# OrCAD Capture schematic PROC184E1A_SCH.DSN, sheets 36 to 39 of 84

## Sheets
36 40. RESET INPUTS: size C; title: RESET INPUTS; note: PROC184_SCH
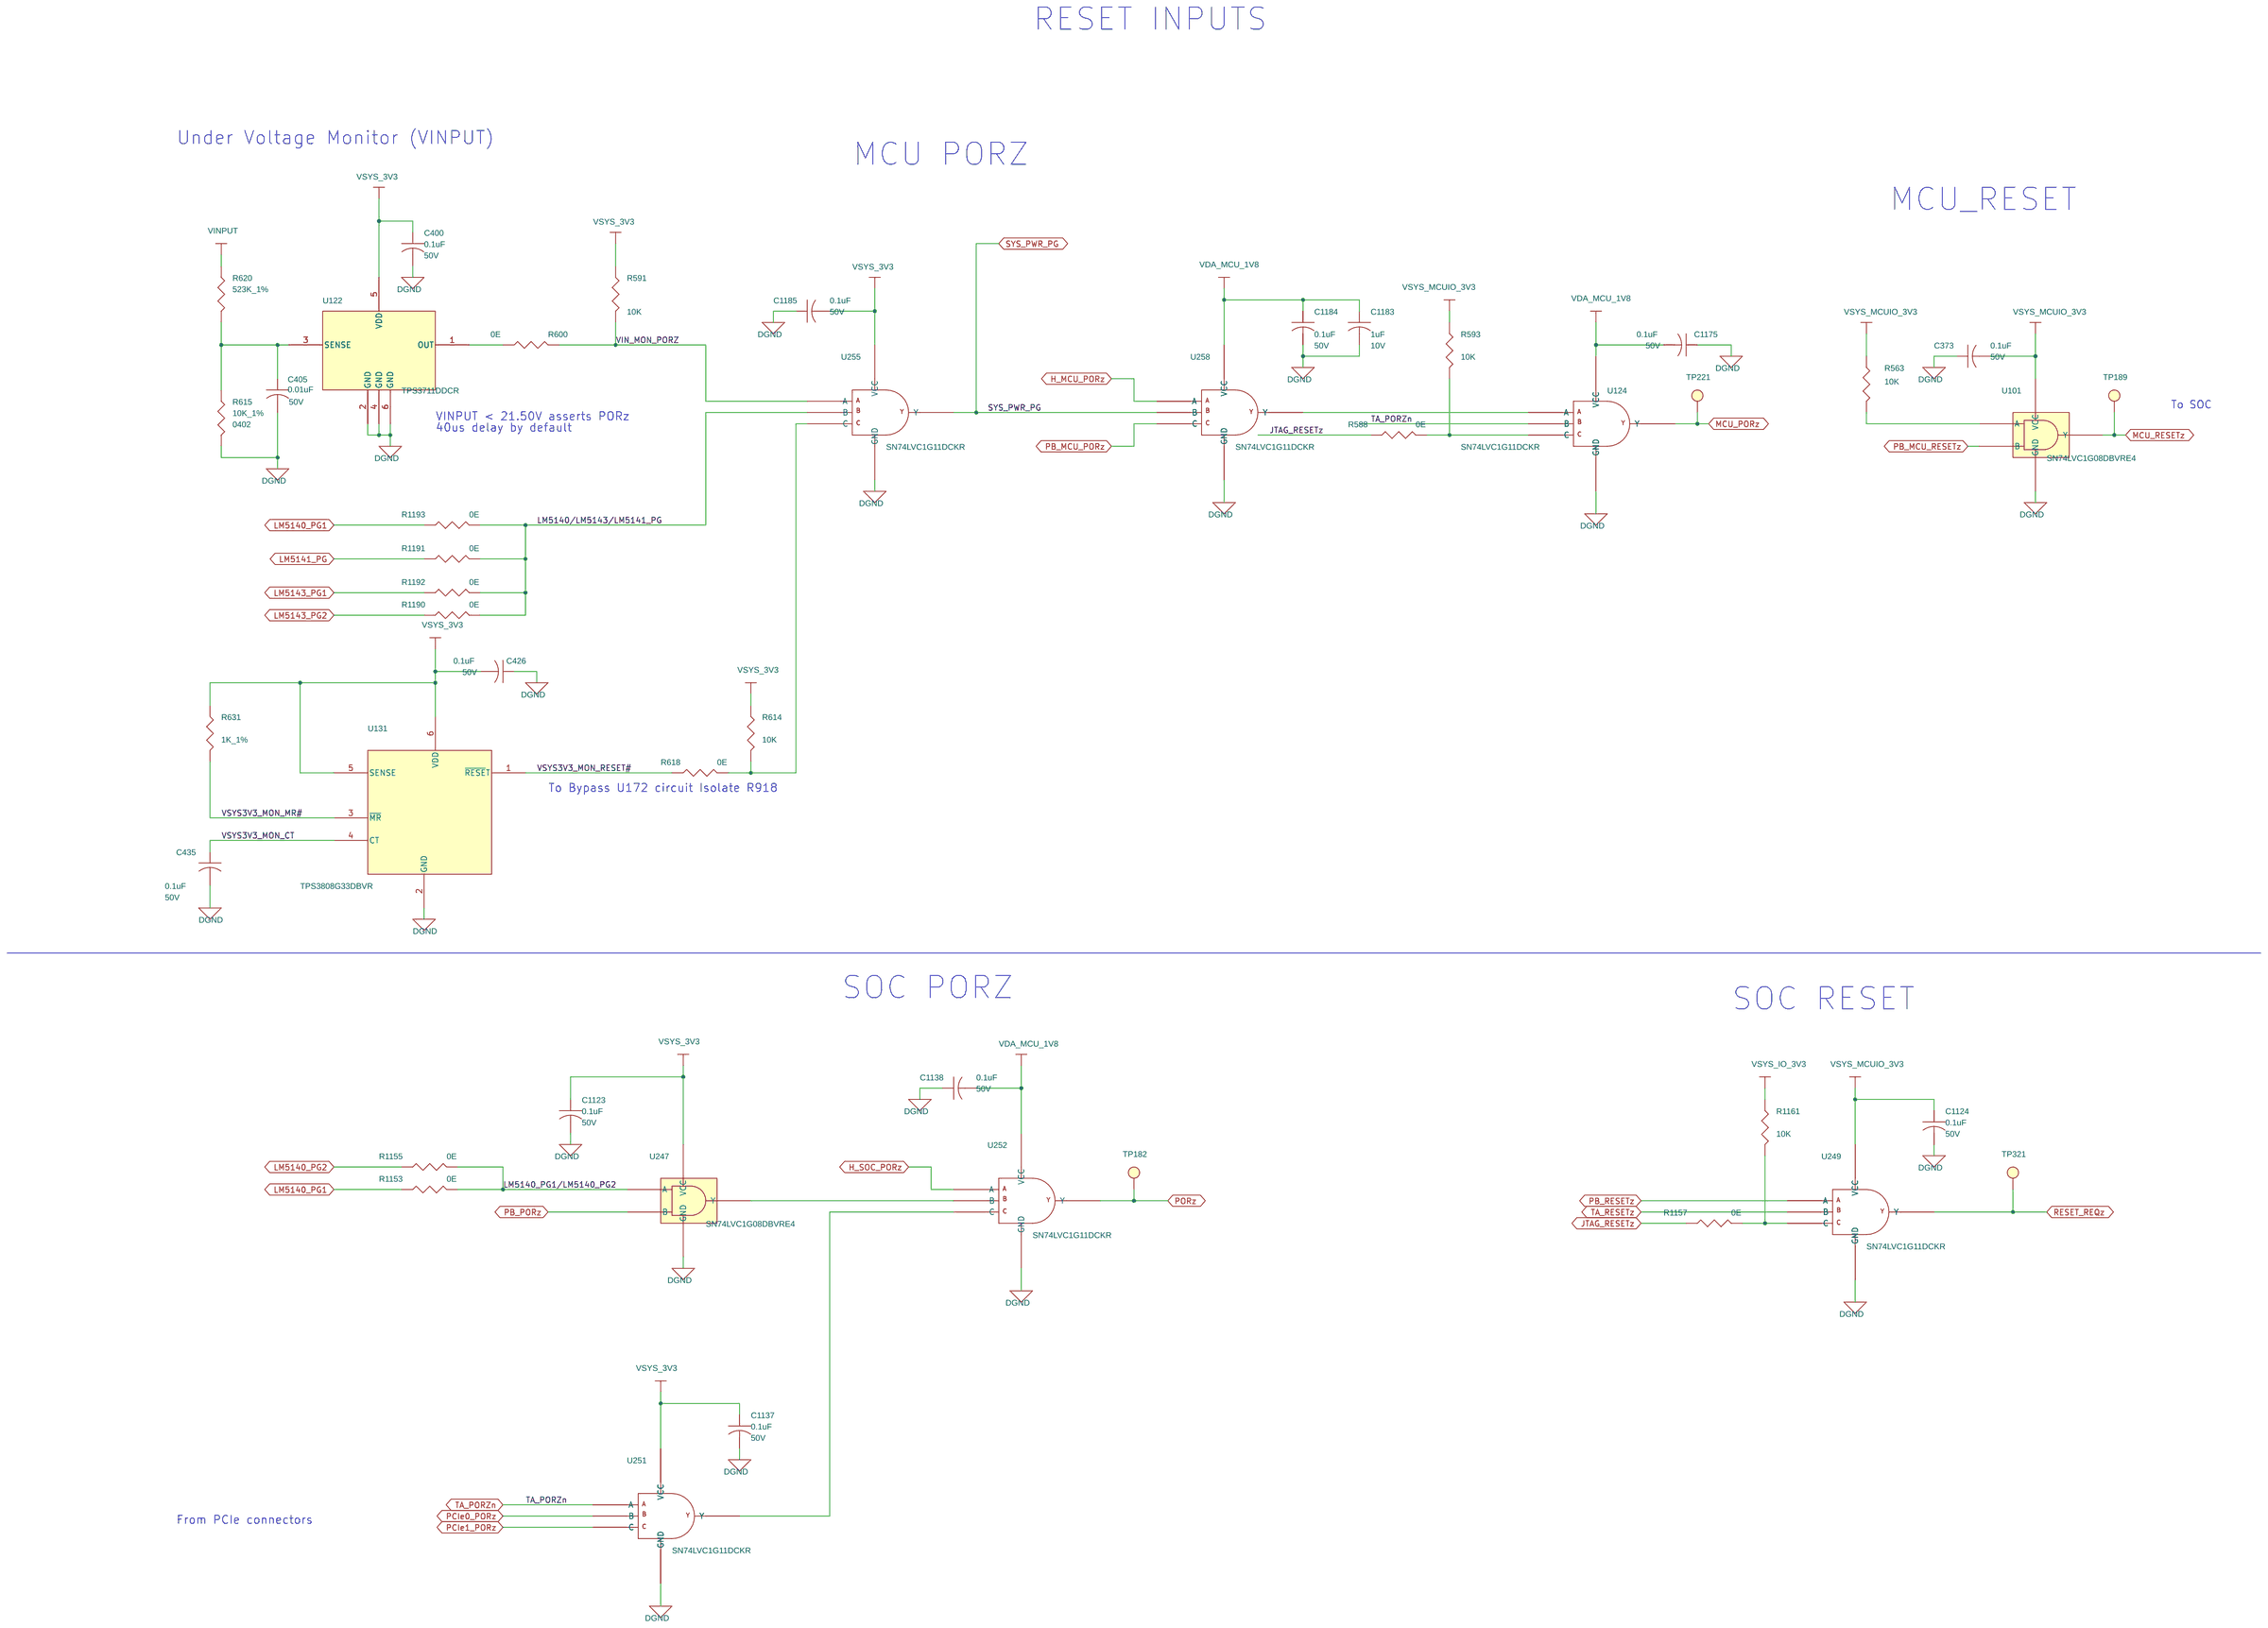
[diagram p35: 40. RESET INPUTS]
37 41. RESET OUTPUTS: size C; title: RESET OUTPUTS; note: PROC184_SCH
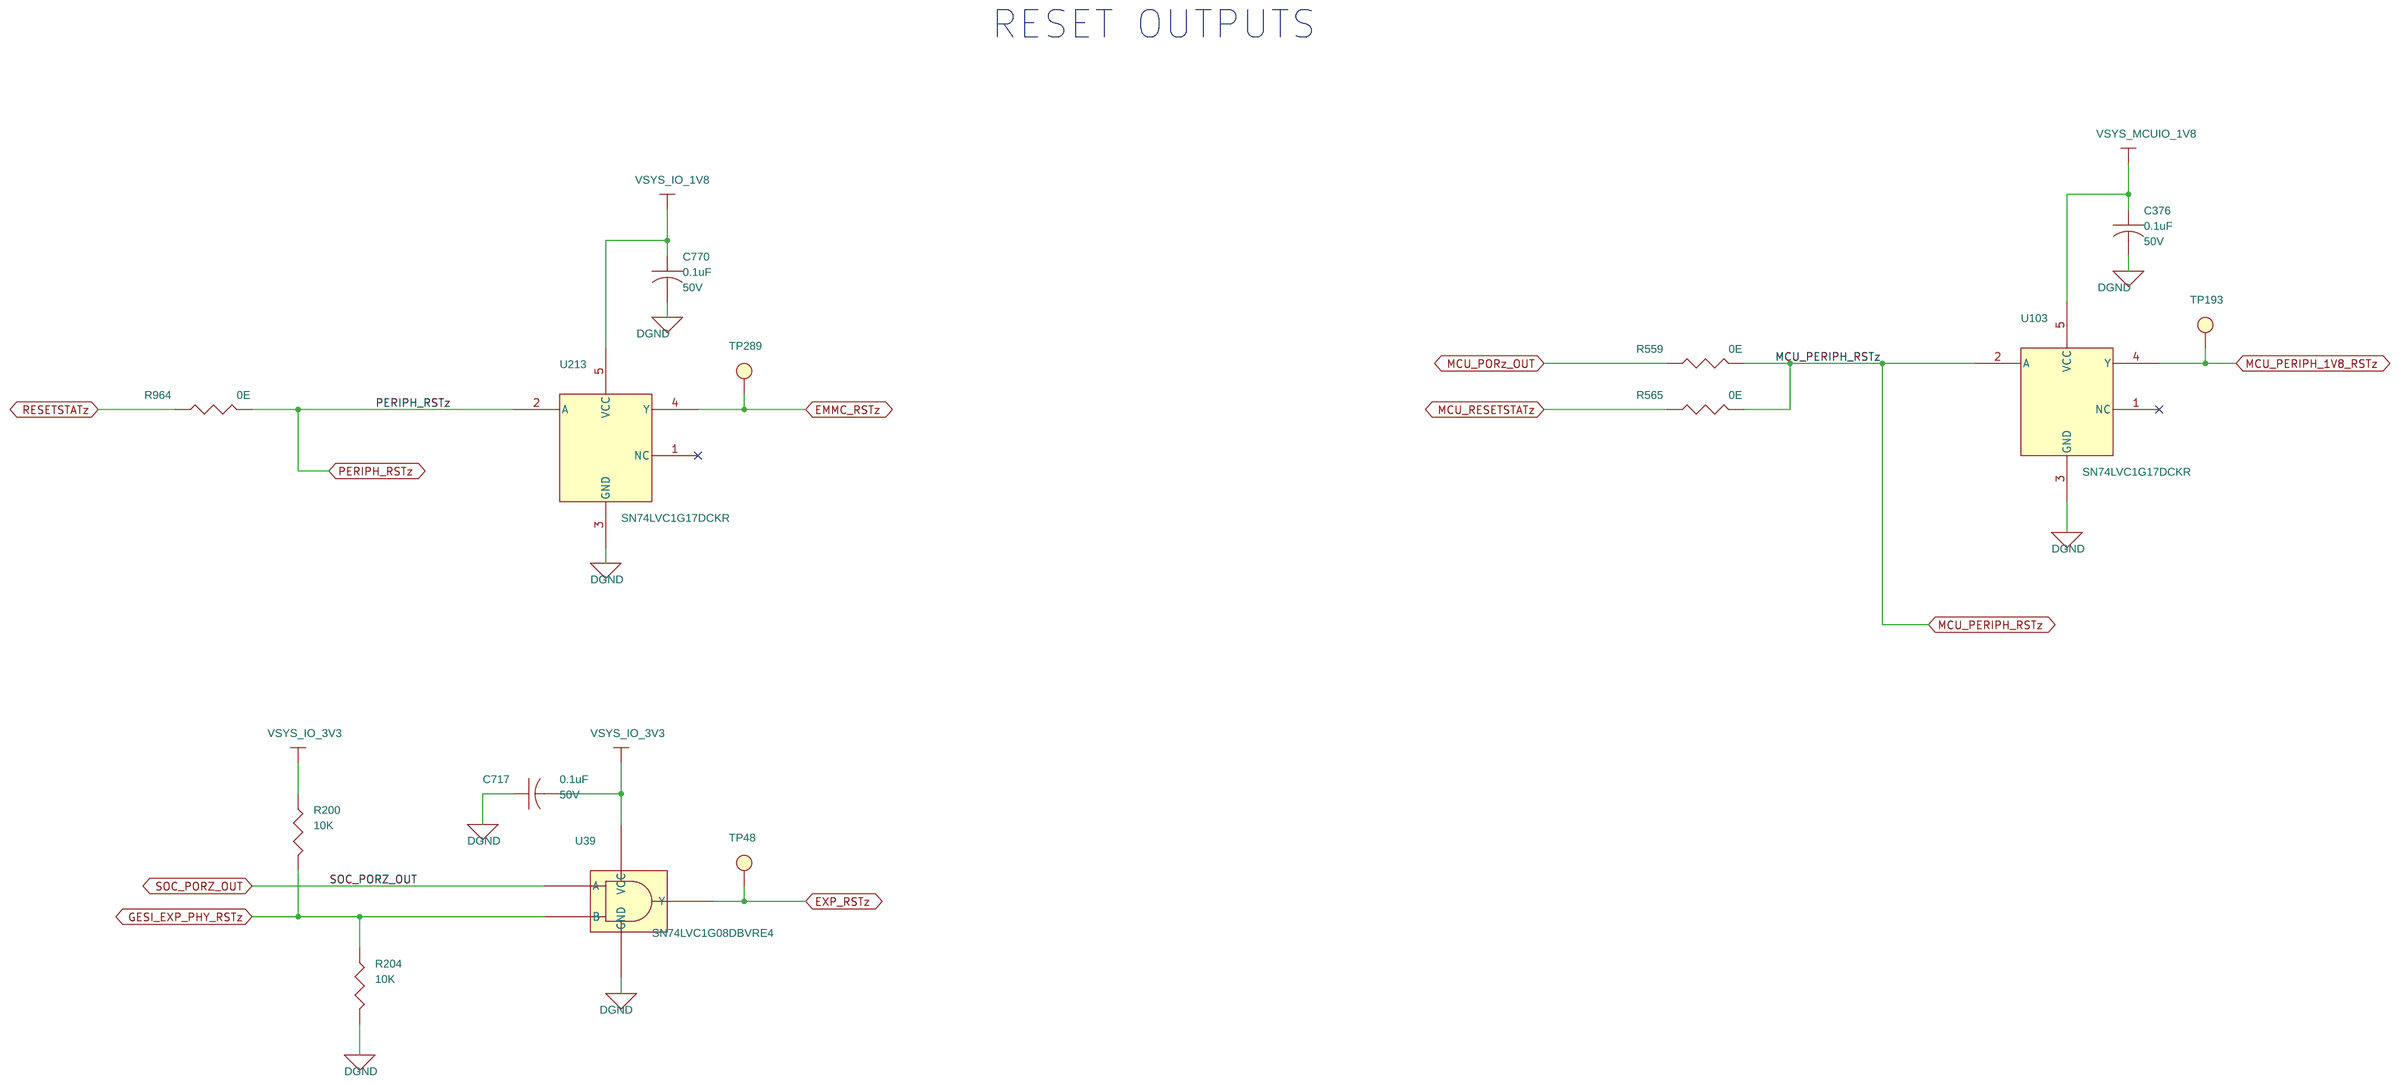
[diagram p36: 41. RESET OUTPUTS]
38 42. GPIO EXPANDERS: size C; title: GPIO  EXPANDERS; note: PROC184_SCH
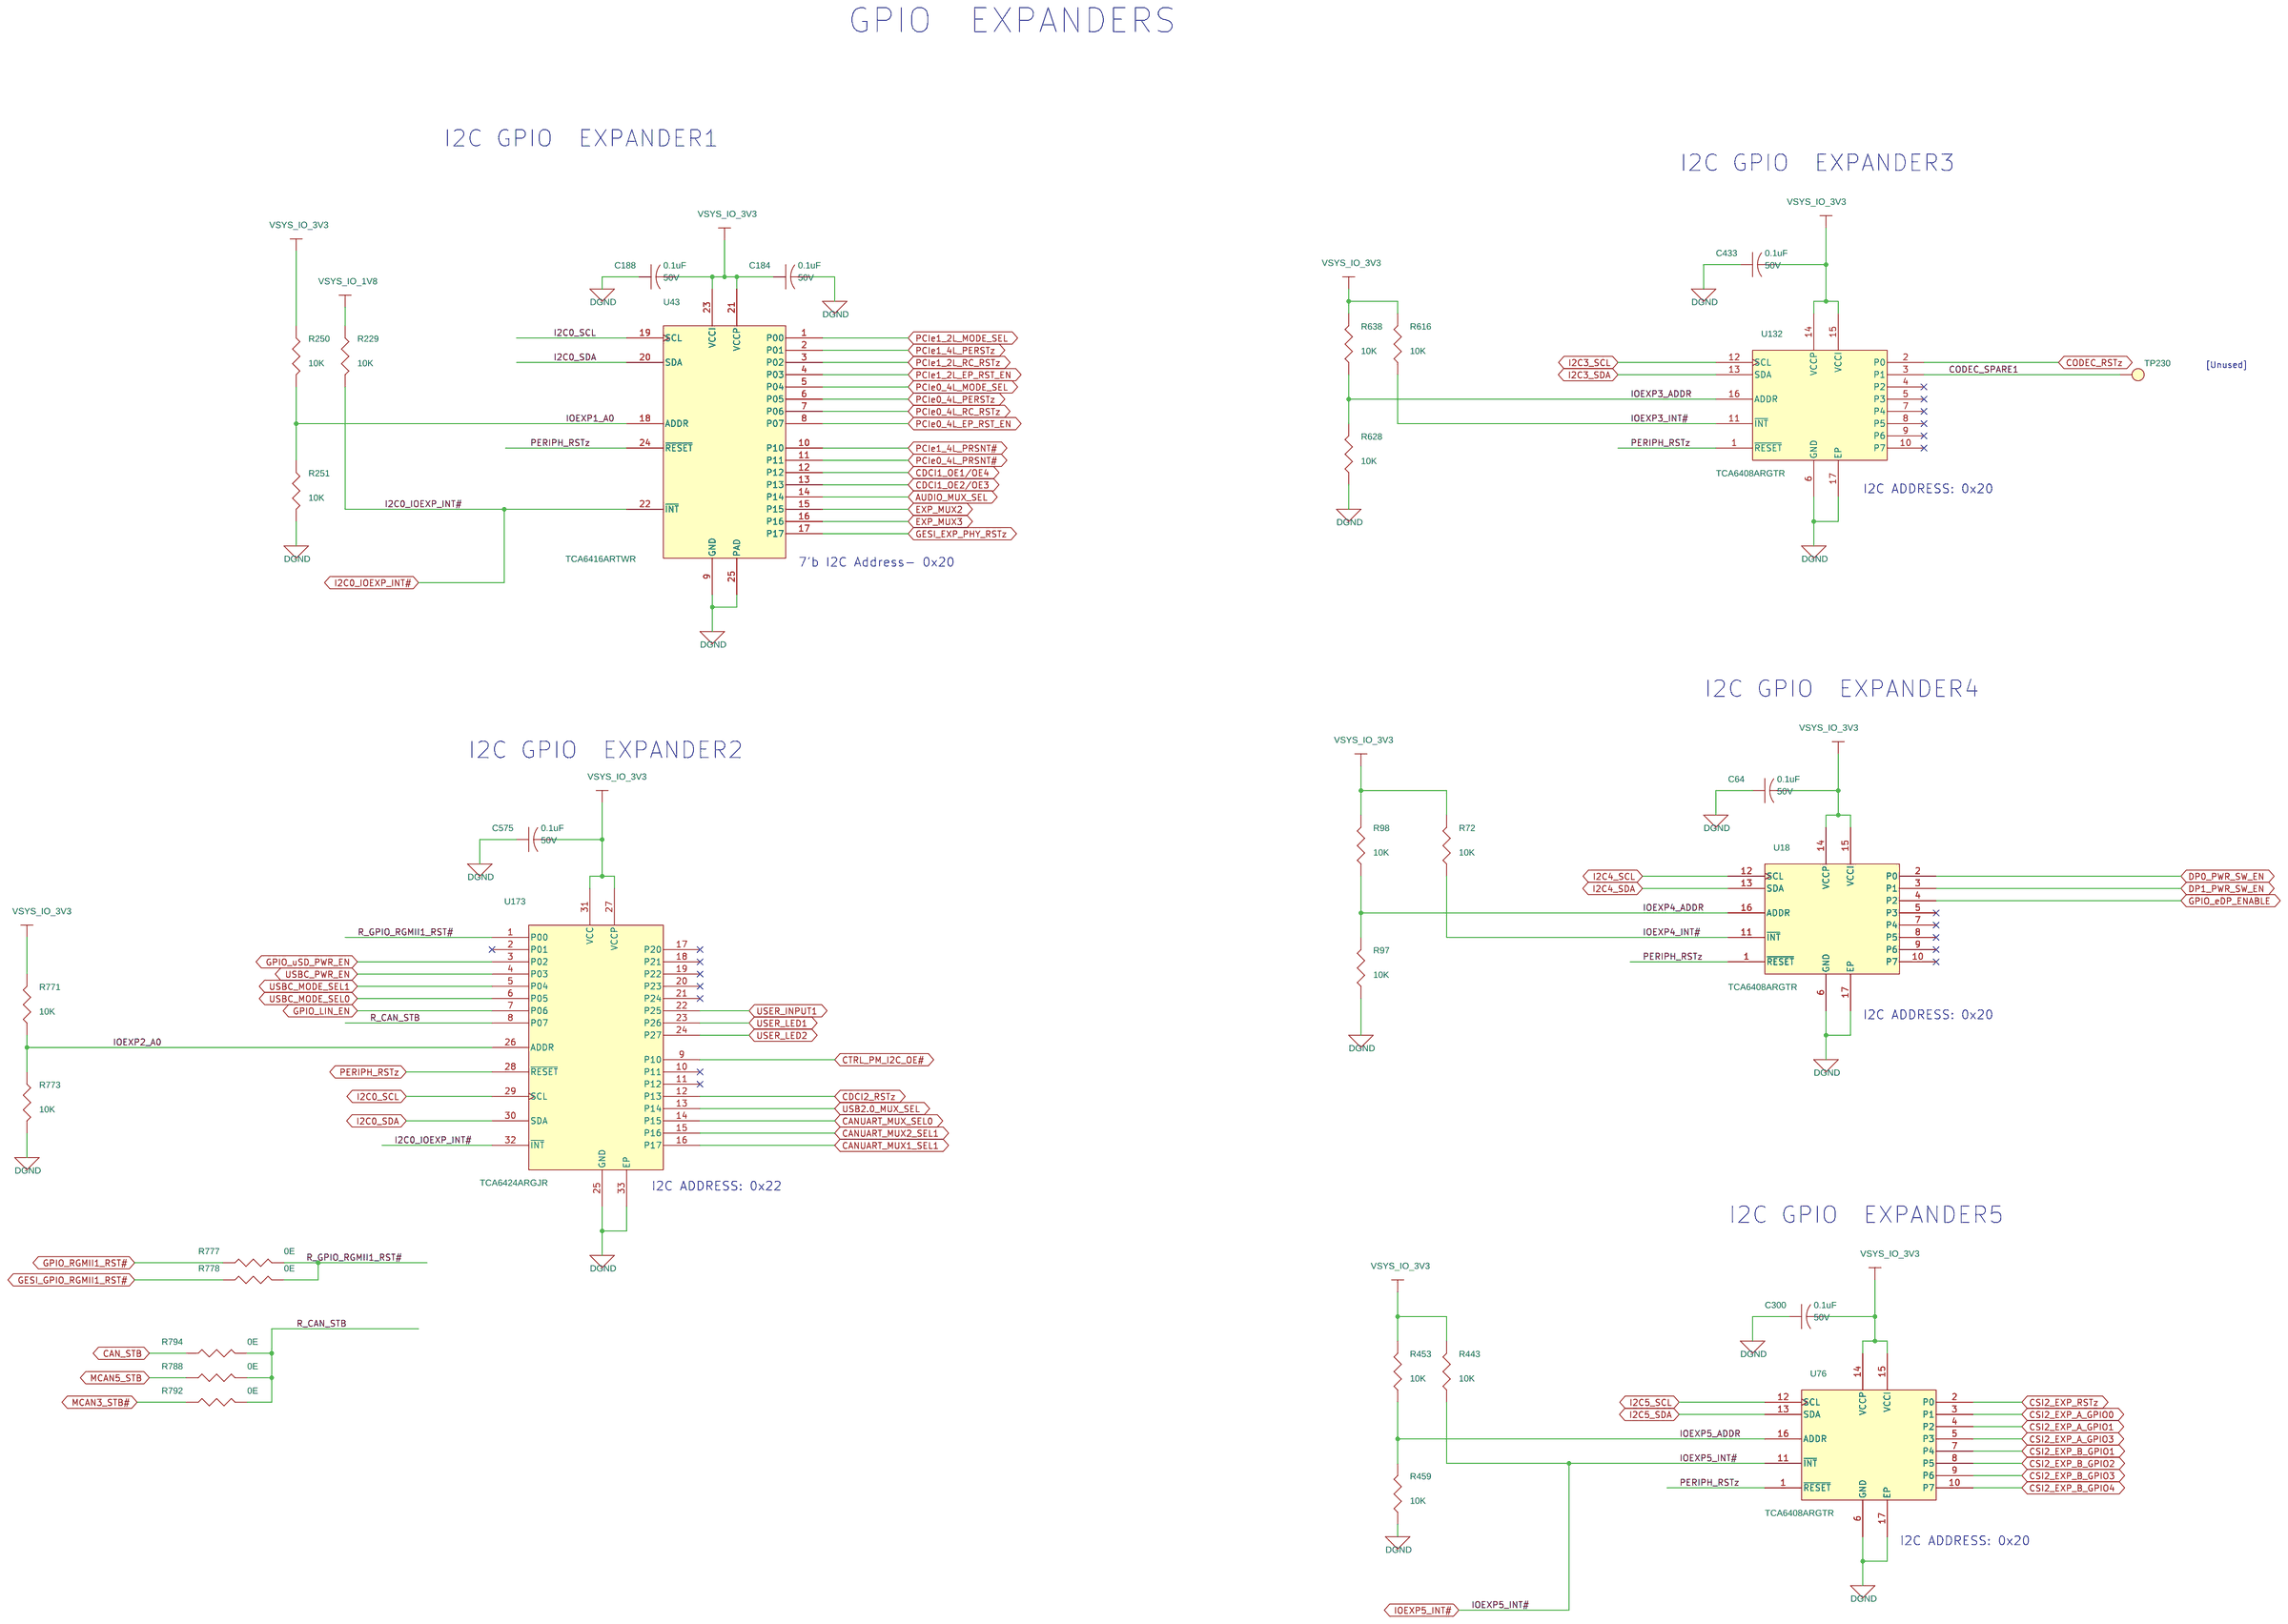
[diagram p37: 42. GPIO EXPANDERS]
39 43. SPI NOR FLASH: size C; title: SPI NOR FLASH; note: PROC184_SCH
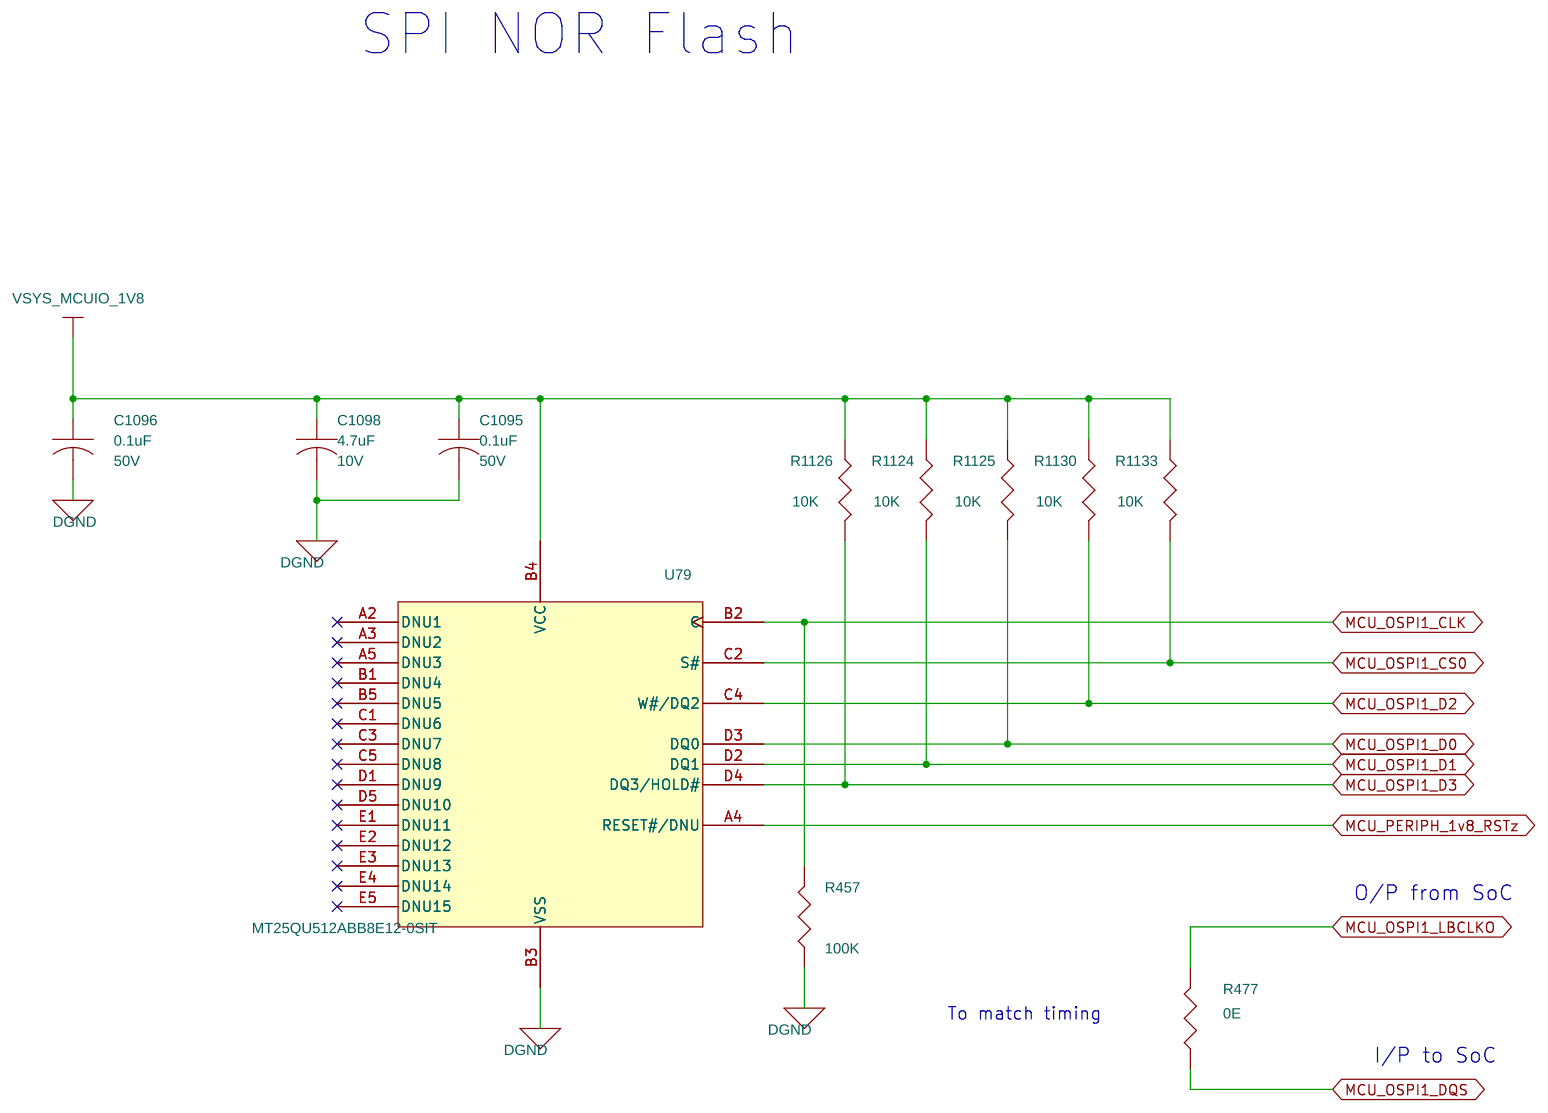
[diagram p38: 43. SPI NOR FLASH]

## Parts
sheet 40. RESET INPUTS
C373  0.1uF  [CAP0402_0-75]
C400  0.1uF  [CAP0402_0-75]
C405  0.01uF  [CAP0402_0-75]
C426  0.1uF  [CAP0402_0-75]
C435  0.1uF  [CAP0402_0-75]
C1123  0.1uF  [CAP0402_0-75]
C1124  0.1uF  [CAP0402_0-75]
C1137  0.1uF  [CAP0402_0-75]
C1138  0.1uF  [CAP0402_0-75]
C1175  0.1uF  [CAP0402_0-75]
C1183  1uF  [CAP0402_0-75]
C1184  0.1uF  [CAP0402_0-75]
C1185  0.1uF  [CAP0402_0-75]
R563  10K  [RES0402_0-5]
R588  0E  [RES0402_0-5]
R591  10K  [RES0402_0-5]
R593  10K  [RES0402_0-5]
R600  0E  [RES0402_0-5]
R614  10K  [RES0402_0-5]
R615  10K_1%  [RES0402_0-5]
R618  0E  [RES0402_0-5]
R620  523K_1%  [RES0402_0-5]
R631  1K_1%  [RES0402_0-5]
R1153  0E  [RES0402_0-5]
R1155  0E  [RES0402_0-5]
R1157  0E  [RES0402_0-5]
R1161  10K  [RES0402_0-5]
R1190  0E  [RES0402_0-5]
R1191  0E  [RES0402_0-5]
R1192  0E  [RES0402_0-5]
R1193  0E  [RES0402_0-5]
TP182  TP40_SMD  [TP40_SMD]
TP189  TP40_SMD  [TP40_SMD]
TP221  TP40_SMD  [TP40_SMD]
TP321  TP40_SMD  [TP40_SMD]
U101  SN74LVC1G08DBVRE4  [SOT23-5]
U122  TPS3711DDCR  [SOT23-6_1-1]
U124  SN74LVC1G11DCKR  [SC70-6]
U131  TPS3808G33DBVR  [SOT23-6_1-5]
U247  SN74LVC1G08DBVRE4  [SOT23-5]
U249  SN74LVC1G11DCKR  [SC70-6]
U251  SN74LVC1G11DCKR  [SC70-6]
U252  SN74LVC1G11DCKR  [SC70-6]
U255  SN74LVC1G11DCKR  [SC70-6]
U258  SN74LVC1G11DCKR  [SC70-6]
sheet 41. RESET OUTPUTS
C376  0.1uF  [CAP0402_0-75]
C717  0.1uF  [CAP0402_0-75]
C770  0.1uF  [CAP0402_0-75]
R200  10K  [RES0402_0-5]
R204  10K  [RES0402_0-5]
R559  0E  [RES0402_0-5]
R565  0E  [RES0402_0-5]
R964  0E  [RES0402_0-5]
TP48  TP40_SMD  [TP40_SMD]
TP193  TP40_SMD  [TP40_SMD]
TP289  TP40_SMD  [TP40_SMD]
U39  SN74LVC1G08DBVRE4  [SOT23-5]
U103  SN74LVC1G17DCKR  [SC70-5]
U213  SN74LVC1G17DCKR  [SC70-5]
sheet 42. GPIO EXPANDERS
C64  0.1uF  [CAP0402_0-75]
C184  0.1uF  [CAP0402_0-75]
C188  0.1uF  [CAP0402_0-75]
C300  0.1uF  [CAP0402_0-75]
C433  0.1uF  [CAP0402_0-75]
C575  0.1uF  [CAP0402_0-75]
R72  10K  [RES0402_0-5]
R97  10K  [RES0402_0-5]
R98  10K  [RES0402_0-5]
R229  10K  [RES0402_0-5]
R250  10K  [RES0402_0-5]
R251  10K  [RES0402_0-5]
R443  10K  [RES0402_0-5]
R453  10K  [RES0402_0-5]
R459  10K  [RES0402_0-5]
R616  10K  [RES0402_0-5]
R628  10K  [RES0402_0-5]
R638  10K  [RES0402_0-5]
R771  10K  [RES0402_0-5]
R773  10K  [RES0402_0-5]
R777  0E  [RES0201_0-5]
R778  0E  [RES0201_0-5]
R788  0E  [RES0402_0-5]
R792  0E  [RES0402_0-5]
R794  0E  [RES0402_0-5]
TP230  TP40_SMD  [TP40_SMD]
U18  TCA6408ARGTR  [QFN16_19-68_120X120_1_EP1-6]
U43  TCA6416ARTWR  [WQFN24_19-68_160X160]
U76  TCA6408ARGTR  [QFN16_19-68_120X120_1_EP1-6]
U132  TCA6408ARGTR  [QFN16_19-68_120X120_1_EP1-6]
U173  TCA6424ARGJR  [QFN32_19-68_200X200]
sheet 43. SPI NOR FLASH
C1095  0.1uF  [CAP0402_0-75]
C1096  0.1uF  [CAP0402_0-75]
C1098  4.7uF  [CAP0402_0-75]
R457  100K  [RES0402_0-5]
R477  0E  [RES0402_0-5]
R1124  10K  [RES0402_0-5]
R1125  10K  [RES0402_0-5]
R1126  10K  [RES0402_0-5]
R1130  10K  [RES0402_0-5]
R1133  10K  [RES0402_0-5]
U79  MT25QU512ABB8E12-0SIT  [TPBGA24_39-37_240X320_1-2]

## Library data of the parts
C64 C184 C188 C300 C373 C376 C400 C426 C433 C575 C717 C770 C1095 C1096 C1123 C1124 C1137 C1138 C1175 C1184 C1185 = CAP: CAP CERAMIC 0.1uF 50V 10% X7R 0402; Automotive Alternate_mfr_name: TDK; Automotive Alternate_mfr_part_number: CGA2B3X7R1H104K050BB; Chkd/date: MANIRAJA/261020; Crtd /date: ALVY/211020; Custom_Duty: 15%; Customs_HS_Code: 85322990; Direct Alternate_mfr_name: TDK; Direct Alternate_mfr_part_number: C1005X7R1H104K050BE; Distributor_name: DIGIKEY; Distributor_part_number: 490-10700-1-ND; Footprint Path: Y:\MIS_DATABASE\Library\ALTIUM_TOOL\PCB_FOOTPRINTS\Altium_Footprint_Lib.PcbLib; Height: 0.55MM; Library Path: Y:\MIS_DATABASE\Library\ALTIUM_TOOL\SCHEMATICS_PARTS\MS_DISCRETE_Library.schlib; Manufacturer: MURATA; Mfr_name: MURATA; Mfr_part_number: GRM155R71H104KE14D; Mistral Part No: 120011100014-R; Package: 0402; Part_type: CAPACITORS\CERAMIC; Project: J7_CP; RoHS: RoHS; Temperature: -55°C+125°C; Tolerance: 10%; Voltage: 50V; Wattage: NA; Weight: 3.1mg; Datasheet: Y:\MIS_DATABASE\DATASHEETS\CAPACITORS\GRM155R71H104KE14.PDF
C405 = CAP: CAP CERAMIC 0.01uF 50V 10% X7R 0402; Automotive Alternate_mfr_name: TDK; Automotive Alternate_mfr_part_number: CGA2B2X7R1E103K050BA; Chkd/date: MANIRAJA/280319; Crtd /date: MANIRAJA/280319; Custom_Duty: 15%; Customs_HS_Code: 85322990; Direct Alternate_mfr_name: YAGEO AMERICA; Direct Alternate_mfr_part_number: CC0402KRX7R8BB103; Distributor_name: DIGIKEY; Distributor_part_number: 490-4516-1-ND; Footprint Path: Y:\MIS_DATABASE\Library\ALTIUM_TOOL\PCB_FOOTPRINTS\Altium_Footprint_Lib.PcbLib; Height: 0.55MM; Library Path: Y:\MIS_DATABASE\Library\ALTIUM_TOOL\SCHEMATICS_PARTS\MS_DISCRETE_Library.schlib; Manufacturer: MURATA; Mfr_name: MURATA; Mfr_part_number: GRM155R71H103KA88D; Mistral Part No: 120009030025-R; Package: 0402; Part_type: CAPACITORS\CERAMIC; Project: G4_SVGA; RoHS: RoHS; Temperature: -55°C+125°C; Tolerance: 10%; Voltage: 50V; Wattage: NA; Weight: 0.65mg; Datasheet: Y:\MIS_DATABASE\DATASHEETS\CAPACITORS\GRM155R71H103KA88D.PDF
C435 = CAP: CAP CERAMIC 0.1uF 50V 10% X7R 0402; Assembly_Instruction: DNI; Automotive Alternate_mfr_name: TDK; Automotive Alternate_mfr_part_number: CGA2B3X7R1H104K050BB; Chkd/date: MANIRAJA/261020; Crtd /date: ALVY/211020; Custom_Duty: 15%; Customs_HS_Code: 85322990; Direct Alternate_mfr_name: TDK; Direct Alternate_mfr_part_number: C1005X7R1H104K050BE; Distributor_name: DIGIKEY; Distributor_part_number: 490-10700-1-ND; Footprint Path: Y:\MIS_DATABASE\Library\ALTIUM_TOOL\PCB_FOOTPRINTS\Altium_Footprint_Lib.PcbLib; Height: 0.55MM; Library Path: Y:\MIS_DATABASE\Library\ALTIUM_TOOL\SCHEMATICS_PARTS\MS_DISCRETE_Library.schlib; Manufacturer: MURATA; Mfr_name: MURATA; Mfr_part_number: GRM155R71H104KE14D; Mistral Part No: 120011100014-R; Package: 0402; Part_type: CAPACITORS\CERAMIC; Project: J7_CP; RoHS: RoHS; Temperature: -55°C+125°C; Tolerance: 10%; Voltage: 50V; Wattage: NA; Weight: 3.1mg; Datasheet: Y:\MIS_DATABASE\DATASHEETS\CAPACITORS\GRM155R71H104KE14.PDF
C1183 = CAP: CAP CERAMIC 1uF 10V 10% X7S AUTO 0402; Automotive Alternate_mfr_name: TAIYO YUDEN; Automotive Alternate_mfr_part_number: EMK105BJ105KVHF; Chkd/date: MANIRAJA/100918; Crtd /date: ALVY/100918; Custom_Duty: 15%; Customs_HS_Code: 85322990; Direct Alternate_mfr_name: YAGEO AMERICA; Direct Alternate_mfr_part_number: CC0402KRX5R7BB105; Distributor_name: DIGIKEY; Distributor_part_number: 490-13409-1-ND; Footprint Path: Y:\MIS_DATABASE\Library\ALTIUM_TOOL\PCB_FOOTPRINTS\Altium_Footprint_Lib.PcbLib; Height: 0.70MM; Library Path: Y:\MIS_DATABASE\Library\ALTIUM_TOOL\SCHEMATICS_PARTS\MS_DISCRETE_Library.schlib; Manufacturer: TDK CORPORATION; Mfr_name: MURATA; Mfr_part_number: GCM155C71A105KE38D; Mistral Part No: 120018090021-R; Package: 0402; Part_type: CAPACITORS\CERAMIC; Project: SMART-M_SCRIPTALK_PB; RoHS: RoHS; Temperature: -55°C+125°C; Tolerance: 10%; Voltage: 10V; Wattage: NA; Weight: 6mg; Datasheet: Y:\MIS_DATABASE\DATASHEETS\CAPACITORS\MURATA-GCM-SER.PDF
R72 R97 R200 R229 R251 R443 R459 R563 R591 R593 R614 R616 R628 R773 R1126 R1130 R1133 R1161 = RESISTOR: RES 10K 1/16W 5% 0402; Chkd/date: VASANTHA/061216; Crtd /date: MAZHAR/230805; Custom_Duty: 15%; Customs_HS_Code: 85332119; Distributor_name: DIGIKEY; Distributor_part_number: 311-10KJRCT-ND; Footprint Path: Y:\MIS_DATABASE\Library\ALTIUM_TOOL\PCB_FOOTPRINTS\Altium_Footprint_Lib.PcbLib; Height: 0.40MM; Library Path: Y:\MIS_DATABASE\Library\ALTIUM_TOOL\SCHEMATICS_PARTS\MS_DISCRETE_Library.schlib; Manufacturer: YAGEO AMERICA; Mfr_name: YAGEO AMERICA; Mfr_part_number: RC0402JR-0710KL; Mistral Part No: 110011060021-R; Package: 0402; Part_type: RESISTORS\FIXED; Project: HSE; RoHS: RoHS; Temperature: -55°C+155°C; Tolerance: 5%; Voltage: NA; Wattage: 1/16W; Weight: 0.65mg; Datasheet: Y:\MIS_DATABASE\DATASHEETS\RESISTORS\RCXXXXL-SER_MAR18.PDF
R477 R565 R588 R600 R618 R788 R792 R794 R964 R1153 R1155 R1157 R1190 R1192 R1193 = RESISTOR: RES 0E 1/10W JUMPER 0402; Chkd/date: VASANTHA/061216; Crtd /date: NAVEED/201014; Custom_Duty: 15%; Customs_HS_Code: 85332119; Distributor_name: DIGIKEY; Distributor_part_number: P0.0JCT-ND; Footprint Path: Y:\MIS_DATABASE\Library\ALTIUM_TOOL\PCB_FOOTPRINTS\Altium_Footprint_Lib.PcbLib; Height: 0.40MM; IBISSP_MODLES: VALUE REPEATING 2 TIME; Library Path: Y:\MIS_DATABASE\Library\ALTIUM_TOOL\SCHEMATICS_PARTS\MS_DISCRETE_Library.schlib; Manufacturer: PANASONIC-ECG; Mfr_name: PANASONIC-ECG; Mfr_part_number: ERJ-2GE0R00X; Mistral Part No: 110018030052-R; Package: 0402; Part_type: RESISTORS\FIXED; Project: AEGIS POM; RoHS: RoHS; Temperature: -55°C+155°C; Tolerance: NA; Voltage: NA; Wattage: 1/10W; Weight: 0.8mg; Datasheet: Y:\MIS_DATABASE\DATASHEETS\RESISTORS\PAN-ERJSER_NOV17.PDF
R615 = RESISTOR: RES 10K 1/16W 1% 0402; Chkd/date: VASANTHA/201216; Crtd /date: GEETHA/290506; Custom_Duty: 15%; Customs_HS_Code: 85332119; Distributor_name: DIGIKEY; Distributor_part_number: 311-10.0KLRTR-ND; Footprint Path: Y:\MIS_DATABASE\Library\ALTIUM_TOOL\PCB_FOOTPRINTS\Altium_Footprint_Lib.PcbLib; Height: 0.40MM; Library Path: Y:\MIS_DATABASE\Library\ALTIUM_TOOL\SCHEMATICS_PARTS\MS_DISCRETE_Library.schlib; Manufacturer: YAGEO AMERICA; Mfr_name: YAGEO AMERICA; Mfr_part_number: RC0402FR-0710KL; Mistral Part No: 110015090015-R; Package: 0402; Part_type: RESISTORS\FIXED; Project: VOCERA; RoHS: RoHS; Temperature: -55°C+155°C; Tolerance: 1%; Voltage: NA; Wattage: 1/16W; Weight: 0.65mg; Datasheet: Y:\MIS_DATABASE\DATASHEETS\RESISTORS\RCXXXXL-SER_MAR18.PDF
R620 = RESISTOR: RES 523K 1/10W 1% 0402; Chkd/date: MANIRAJA/111219; Crtd /date: ALVY/111219; Custom_Duty: 15%; Customs_HS_Code: 85332119; Distributor_name: DIGIKEY; Distributor_part_number: P523KLCT-ND; Footprint Path: Y:\MIS_DATABASE\Library\ALTIUM_TOOL\PCB_FOOTPRINTS\Altium_Footprint_Lib.PcbLib; Height: 0.40MM; Library Path: Y:\MIS_DATABASE\Library\ALTIUM_TOOL\SCHEMATICS_PARTS\MS_DISCRETE_Library.schlib; Manufacturer: PANASONIC-ECG; Mfr_name: PANASONIC-ECG; Mfr_part_number: ERJ-2RKF5233X; Mistral Part No: 110019120010-R; Package: 0402; Part_type: RESISTORS\FIXED; Project: CLOUD RADAR_CONTROLLER-PS_BRD; RoHS: RoHS; Temperature: -55°C+155°C; Tolerance: 1%; Voltage: NA; Wattage: 1/10W; Weight: 0.8mg; Datasheet: Y:\MIS_DATABASE\DATASHEETS\RESISTORS\PAN-ERJSER_NOV17.PDF
R631 = RESISTOR: RES 1K 1/10W 1% 0402; Chkd/date: VASANTHA/281216; Crtd /date: MAZHAR/150506; Custom_Duty: 15%; Customs_HS_Code: 85332119; Distributor_name: DIGIKEY; Distributor_part_number: P1.00KLCT-ND; Footprint Path: Y:\MIS_DATABASE\Library\ALTIUM_TOOL\PCB_FOOTPRINTS\Altium_Footprint_Lib.PcbLib; Height: 0.40MM; Library Path: Y:\MIS_DATABASE\Library\ALTIUM_TOOL\SCHEMATICS_PARTS\MS_DISCRETE_Library.schlib; Manufacturer: PANASONIC-ECG; Mfr_name: PANASONIC-ECG; Mfr_part_number: ERJ-2RKF1001X; Mistral Part No: 110009030411-R; Package: 0402; Part_type: RESISTORS\FIXED; Project: VOCERA; RoHS: RoHS; Temperature: -55°C+155°C; Tolerance: 1%; Voltage: NA; Wattage: 1/10W; Weight: 0.8mg; Datasheet: Y:\MIS_DATABASE\DATASHEETS\RESISTORS\PAN-ERJSER_NOV17.PDF
R559 R1191 = RESISTOR: RES 0E 1/10W JUMPER 0402; Assembly_Instruction: DNI; Chkd/date: VASANTHA/061216; Crtd /date: NAVEED/201014; Custom_Duty: 15%; Customs_HS_Code: 85332119; Distributor_name: DIGIKEY; Distributor_part_number: P0.0JCT-ND; Footprint Path: Y:\MIS_DATABASE\Library\ALTIUM_TOOL\PCB_FOOTPRINTS\Altium_Footprint_Lib.PcbLib; Height: 0.40MM; IBISSP_MODLES: VALUE REPEATING 2 TIME; Library Path: Y:\MIS_DATABASE\Library\ALTIUM_TOOL\SCHEMATICS_PARTS\MS_DISCRETE_Library.schlib; Manufacturer: PANASONIC-ECG; Mfr_name: PANASONIC-ECG; Mfr_part_number: ERJ-2GE0R00X; Mistral Part No: 110018030052-R; Package: 0402; Part_type: RESISTORS\FIXED; Project: AEGIS POM; RoHS: RoHS; Temperature: -55°C+155°C; Tolerance: NA; Voltage: NA; Wattage: 1/10W; Weight: 0.8mg; Datasheet: Y:\MIS_DATABASE\DATASHEETS\RESISTORS\PAN-ERJSER_NOV17.PDF
TP48 TP182 TP189 TP193 TP221 TP230 TP289 TP321 = TESTPOINT: TESTPOINT CIR 40 SMD; Chkd/date: MAZHAR/190505; Crtd /date: MAZHAR/190505; Distributor_name: NA; Distributor_part_number: NA; Footprint Path: Y:\MIS_DATABASE\Library\ALTIUM_TOOL\PCB_FOOTPRINTS\Altium_Footprint_Lib.PcbLib; Height: NA; Library Path: Y:\MIS_DATABASE\Library\ALTIUM_TOOL\SCHEMATICS_PARTS\MS_DISCRETE_Library.schlib; MECHANICAL 3D STEP FILE: NA; Manufacturer: LOCAL; Mfr_name: LOCAL; Mistral Part No: 130009030933; Package: SMD; Project: RAINIER-3; RoHS: NA; Temperature: NA; Tolerance: NA; Voltage: NA; Wattage: NA; Weight: NA; Datasheet: NA
U39 U101 U247 = SN74LVC1G08DBVRE4_SOT23-5: IC SINGLE 2-INPUT POSITIVE AND GATE SOT23-5; Automotive Alternate_mfr_name: TEXAS INSTRUMENTS; Automotive Alternate_mfr_part_number: SN74LVC1G08QDBVRQ1; Chkd/date: SUHAS/221010; Crtd /date: USMAN/151008; Custom_Duty: 15%; Customs_HS_Code: 85423100; Distributor_name: DIGIKEY; Distributor_part_number: SN74LVC1G08DBVRE4-ND; Height: 1.45MM; Manufacturer: TEXAS INSTRUMENTS; Mfr_name: TEXAS INSTRUMENTS; Mistral Part No: 141009060026-R; Part_type: ICS\DIGITAL\GATES; Project: KHAN_MAIN; RoHS: Sb/ Br FREE; Temperature: -40°C+85°C; Datasheet: Y:\MIS_DATABASE\DATASHEETS\ICS\DIGITAL\GATES\SN74LVC1G08.PDF
U122 = TPS3711DDCR_SOT23-6: IC 36V VOLTAGE DETECTOR SOT23-6; Chkd/date: MANIRAJA/091017; Crtd /date: MANIRAJA/091017; Custom_Duty: 15%; Customs_HS_Code: 85423100; Distributor_name: DIGIKEY; Distributor_part_number: 296-43278-1-ND; Height: 1.10MM; Manufacturer: TEXAS INSTRUMENTS; Mfr_name: TEXAS INSTRUMENTS; Mistral Part No: 142017100008-R; Package: SOT23-6; Part_type: ICS\POWER\MANAGEMENT; Project: TI_MAXIE_CPB; RoHS: RoHS; Temperature: -40°C+125°C; Tolerance: NA; Voltage: NA; Wattage: NA; Weight: 30mg; Datasheet: Y:\MIS_DATABASE\DATASHEETS\ICS\POWER\TPS3711D.PDF
U124 = SN74LVC1G11DCKR_SC70-6: IC SINGLE 3-INPUT POSITIVE-AND GATE SC70-6; Chkd/date: SHREESHAIL/220506; Crtd /date: MAZHAR/150506; Custom_Duty: 15%; Customs_HS_Code: 85423100; Distributor_name: DIGIKEY; Distributor_part_number: 296-18066-1-ND; Height: 1.10MM; Manufacturer: TEXAS INSTRUMENTS; Mfr_name: TEXAS INSTRUMENTS; Mistral Part No: 141009030230-R; Part_type: ICS\DIGITAL\GATES; Project: VOCERA; RoHS: Sb/ Br FREE; Datasheet: Y:\MIS_DATABASE\DATASHEETS\ICS\DIGITAL\GATES\SN74LVC1G.PDF
U131 = TPS3808G33DBV_SOT23-6: IC 3.3V LOW QUIESCENT CURRENT PROGRAMMABLE DELAY SUPERVISORY CIRCUIT SOT23-6; Automotive Alternate_mfr_name: TEXAS INSTRUMENTS; Automotive Alternate_mfr_part_number: TPS3808G33QDBVRQ1; Chkd/date: SUHAS/050411; Crtd /date: MAZHAR/031210; Custom_Duty: 15%; Customs_HS_Code: 85423100; Distributor_name: DIGIKEY; Distributor_part_number: 296-17195-1-ND; Footprint Path: Y:\MIS_DATABASE\Library\ALTIUM_TOOL\PCB_FOOTPRINTS\Altium_Footprint_Lib.PcbLib; Height: 1.45MM; Library Path: Y:\MIS_DATABASE\Library\ALTIUM_TOOL\SCHEMATICS_PARTS\MS_MISCPOWER_Library.schlib; Manufacturer: TEXAS INSTRUMENTS; Mfr_name: TEXAS INSTRUMENTS; Mistral Part No: 142010120003-R; Package: SOT23-6; Part_type: ICS\POWER; Project: IEMS; RoHS: RoHS; Temperature: -40°C+125°C; Tolerance: NA; Voltage: NA; Wattage: NA; Weight: 36mg; Datasheet: Y:\MIS_DATABASE\DATASHEETS\ICS\POWER\TPS3808.PDF
U249 U251 U252 U255 U258 = SN74LVC1G11DCKR_SC70-6: IC SINGLE 3-INPUT POSITIVE-AND GATE SC70-6; Automotive Alternate_mfr_name: TEXAS INSTRUMENTS; Automotive Alternate_mfr_part_number: SN74LVC1G11IDCKRQ1; Chkd/date: SHREESHAIL/220506; Crtd /date: MAZHAR/150506; Custom_Duty: 15%; Customs_HS_Code: 85423100; Distributor_name: DIGIKEY; Distributor_part_number: 296-18066-1-ND; Height: 1.10MM; Manufacturer: TEXAS INSTRUMENTS; Mfr_name: TEXAS INSTRUMENTS; Mistral Part No: 141009030230-R; Part_type: ICS\DIGITAL\GATES; Project: VOCERA; RoHS: Sb/ Br FREE; Datasheet: Y:\MIS_DATABASE\DATASHEETS\ICS\DIGITAL\GATES\SN74LVC1G.PDF
R98 R204 R250 R453 R638 R771 R1124 R1125 = RESISTOR: RES 10K 1/16W 5% 0402; Assembly_Instruction: DNI; Chkd/date: VASANTHA/061216; Crtd /date: MAZHAR/230805; Custom_Duty: 15%; Customs_HS_Code: 85332119; Distributor_name: DIGIKEY; Distributor_part_number: 311-10KJRCT-ND; Footprint Path: Y:\MIS_DATABASE\Library\ALTIUM_TOOL\PCB_FOOTPRINTS\Altium_Footprint_Lib.PcbLib; Height: 0.40MM; Library Path: Y:\MIS_DATABASE\Library\ALTIUM_TOOL\SCHEMATICS_PARTS\MS_DISCRETE_Library.schlib; Manufacturer: YAGEO AMERICA; Mfr_name: YAGEO AMERICA; Mfr_part_number: RC0402JR-0710KL; Mistral Part No: 110011060021-R; Package: 0402; Part_type: RESISTORS\FIXED; Project: HSE; RoHS: RoHS; Temperature: -55°C+155°C; Tolerance: 5%; Voltage: NA; Wattage: 1/16W; Weight: 0.65mg; Datasheet: Y:\MIS_DATABASE\DATASHEETS\RESISTORS\RCXXXXL-SER_MAR18.PDF
U103 U213 = SN74LVC1G17DCKR_SC70-5: IC SINGLE SCHMITT-TRIGGER BUFFER SC70-5; Automotive Alternate_mfr_name: TEXAS INSTRUMENTS; Automotive Alternate_mfr_part_number: SN74LVC1G17QDCKRQ1; Chkd/date: MAZHAR/011210; Crtd /date: BAVISH/251110; Custom_Duty: 15%; Customs_HS_Code: 85423100; Distributor_name: DIGIKEY; Distributor_part_number: 296-11934-1-ND; Height: 1.10MM; Manufacturer: TEXAS INSTRUMENTS; Mfr_name: TEXAS INSTRUMENTS; Mistral Part No: 141010110012-R; Part_type: ICS\DIGITAL\COMBINATIONAL; Project: ITS-PWR_CARD; RoHS: RoHS; Temperature: -40°C+85°C; Tolerance: NA; Voltage: NA; Wattage: NA; Weight: NA; Datasheet: Y:\MIS_DATABASE\DATASHEETS\ICS\DIGITAL\COMBINATIONAL\SN74LVC1G17DCK.PDF
R777 R778 = RESISTOR: RES 0E 1/20W 5% 0201; Chkd/date: NAVEED/301214; Crtd /date: MUDDU/120710; Custom_Duty: 15%; Customs_HS_Code: 85332119; Distributor_name: DIGIKEY; Distributor_part_number: 311-0.0NCT-ND; Footprint Path: Y:\MIS_DATABASE\Library\ALTIUM_TOOL\PCB_FOOTPRINTS\Altium_Footprint_Lib.PcbLib; Height: 0.26MM; Library Path: Y:\MIS_DATABASE\Library\ALTIUM_TOOL\SCHEMATICS_PARTS\MS_DISCRETE_Library.schlib; Manufacturer: YAGEO AMERICA; Mfr_name: YAGEO AMERICA; Mfr_part_number: RC0201JR-070RL; Mistral Part No: 110010070067-R; Package: 0201; Part_type: RESISTORS\FIXED; Project: PB_BUGBASE; RoHS: RoHS; Temperature: -55°C+125°C; Tolerance: 5%; Voltage: NA; Wattage: 1/20W; Weight: 0.17mg; Datasheet: Y:\MIS_DATABASE\DATASHEETS\RESISTORS\RCXXXXL-SER_MAR18.PDF
U18 U76 U132 = TCA6408ARGTR_VQFN16: IC 8-BIT I2C AND SMBUS I/O EXPANDER WITH INTERRUPT O/P VQFN16; Chkd/date: MANIRAJA/151018; Crtd /date: MANIRAJA/151018; Custom_Duty: 15%; Customs_HS_Code: 85423100; Distributor_name: DIGIKEY; Distributor_part_number: 296-24825-1-ND; Footprint Path: Y:\MIS_DATABASE\Library\ALTIUM_TOOL\PCB_FOOTPRINTS\Altium_Footprint_Lib.PcbLib; Height: 1.00MM; Library Path: Y:\MIS_DATABASE\Library\ALTIUM_TOOL\SCHEMATICS_PARTS\MS_MISCINTERFACE_Library.schlib; Manufacturer: TEXAS INSTRUMENTS; Mfr_name: TEXAS INSTRUMENTS; Mistral Part No: 141018100011-R; Package: VQFN16; Part_type: ICS\INTERFACE; Project: TI_60GHz-AOP; RoHS: RoHS; Temperature: -40°C+85°C; Tolerance: NA; Voltage: NA; Wattage: NA; Weight: 24.1mg; Datasheet: Y:\MIS_DATABASE\DATASHEETS\ICS\INTERFACE\TCA6408AXX.PDF
U43 = TCA6416ARTWR_WQFN24: IC I2C I/O EXPANDER 16Bit WQFN24; Chkd/date: VASANTHA/011016; Crtd /date: VASANTHA/011016; Custom_Duty: 15%; Customs_HS_Code: 85423100; Distributor_name: DIGIKEY; Distributor_part_number: 296-24826-1-ND; Height: 0.80MM; Manufacturer: TEXAS INSTRUMENTS; Mfr_name: TEXAS INSTRUMENTS; Mistral Part No: 141016100001-R; Package: WQFN24; Part_type: ICS\DIGITAL\BUSTRANSCEIVER; Project: OCTBTS5200_FEM; RoHS: RoHS; Temperature: -40°C+85°C; Tolerance: NA; Voltage: NA; Wattage: NA; Weight: NA; Datasheet: Y:\MIS_DATABASE\DATASHEETS\ICS\DIGITAL\BUSTRANSCEIVER\TCA6416.PDF
U173 = TCA6424ARGJR_QFN32: IC I2C I/O EXPANDER 24B UQFN32; Chkd/date: NAVEED/100715; Crtd /date: NAVEED/100914; Custom_Duty: 15%; Customs_HS_Code: 85423100; Distributor_name: DIGIKEY; Distributor_part_number: 296-27844-1-ND; Height: 0.60MM; Manufacturer: TEXAS INSTRUMENTS; Mfr_name: TEXAS INSTRUMENTS; Mistral Part No: 141014090009-R; Package: UQFN32; Part_type: ICS\DIGITAL\BUSTRANSCEIVER; Project: ZK_BIOMETRIC; RoHS: RoHS; Temperature: -40°C+85°C; Weight: NA; Datasheet: Y:\MIS_DATABASE\DATASHEETS\ICS\DIGITAL\BUSTRANSCEIVER\TCA6424AR.PDF
C1098 = CAP: CAP CERAMIC 4.7uF 10V 20% X5R 0402; Automotive Alternate_mfr_name: MURATA; Automotive Alternate_mfr_part_number: GRT155R61A475ME13D; Chkd/date: VASANTHA/061216; Crtd /date: CHAITHANYA/070612; Custom_Duty: 15%; Customs_HS_Code: 85322990; Direct Alternate_mfr_name: MURATA; Direct Alternate_mfr_part_number: GRM155R61A475MEAAD; Distributor_name: DIGIKEY; Distributor_part_number: 445-8023-1-ND; Footprint Path: Y:\MIS_DATABASE\Library\ALTIUM_TOOL\PCB_FOOTPRINTS\Altium_Footprint_Lib.PcbLib; Height: 0.55MM; Library Path: Y:\MIS_DATABASE\Library\ALTIUM_TOOL\SCHEMATICS_PARTS\MS_DISCRETE_Library.schlib; Manufacturer: TDK CORPORATION; Mfr_name: TDK CORPORATION; Mfr_part_number: C1005X5R1A475M; Mistral Part No: 120012060002-R; Package: 0402; Part_type: CAPACITORS\CERAMIC; Project: IRIS; RoHS: RoHS; Temperature: -55°C+85°C; Tolerance: 20%; Voltage: 10V; Wattage: NA; Weight: 0.65mg; Datasheet: Y:\MIS_DATABASE\DATASHEETS\CAPACITORS\TDK-C-SER_JUL17.PDF
R457 = RESISTOR: RES 100K 1/10W 5% 0402; Chkd/date: VASANTHA/291216; Crtd /date: GEETHA/190406; Custom_Duty: 15%; Customs_HS_Code: 85332119; Distributor_name: DIGIKEY; Distributor_part_number: P100KJCT-ND; Footprint Path: Y:\MIS_DATABASE\Library\ALTIUM_TOOL\PCB_FOOTPRINTS\Altium_Footprint_Lib.PcbLib; Height: 0.40MM; Library Path: Y:\MIS_DATABASE\Library\ALTIUM_TOOL\SCHEMATICS_PARTS\MS_DISCRETE_Library.schlib; Manufacturer: PANASONIC-ECG; Mfr_name: PANASONIC-ECG; Mfr_part_number: ERJ-2GEJ104X; Mistral Part No: 110009030177-R; Package: 0402; Part_type: RESISTORS\FIXED; Project: RED EYE; RoHS: RoHS; Temperature: -55°C+155°C; Tolerance: 5%; Voltage: NA; Wattage: 1/10W; Weight: 0.8mg; Datasheet: Y:\MIS_DATABASE\DATASHEETS\RESISTORS\PAN-ERJSER_NOV17.PDF
U79 = MT25QL02GCBB8E12_TPBGA24: IC 512Mb SERIAL NOR FLASH MEMORY TPBGA24; Automotive Alternate_mfr_name: MICRON; Automotive Alternate_mfr_part_number: MT25QU512ABB8E12-0AAT TR; Chkd/date: MANIRAJA/251017; Crtd /date: MANIRAJA/251017; Custom_Duty: 15%; Customs_HS_Code: 85423100; Distributor_name: DIGIKEY; Distributor_part_number: MT25QU512ABB8E12-0SIT-ND; Height: 1.20MM; Manufacturer: MICRON; Mfr_name: MICRON; Mistral Part No: 141117100002-R; Package: TPBGA24; Part_type: ICS\DIGITAL\MEMORY; Project: TI_SVB_MAXWELL_HBMC-OSPI; RoHS: RoHS; Temperature: -40°C+85°C; Tolerance: NA; Voltage: NA; Wattage: NA; Weight: NA; Datasheet: Y:\MIS_DATABASE\DATASHEETS\ICS\MEMORY\MT25QX02G.PDF

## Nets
DGND: C64.1 C184.2 C188.1 C300.1 C373.1 C376.2 C400.2 C405.2 C426.1 C433.1 C435.2 C575.1 C717.1 C770.2 C1095.2 C1096.2 C1098.2 C1123.2 C1124.2 C1137.2 C1138.1 C1175.1 C1183.2 C1184.2 C1185.1 R97.1 R204.2 R251.2 R457.1 R459.1 R615.2 R628.1 R773.2 U18.6(GND) U18.17(EP) U39.3(GND) U43.9(GND) U43.25(PAD) U76.6(GND) U76.17(EP) U79.B3(VSS) U101.3(GND) U103.3(GND) U122.2(GND) U122.4(GND) U122.6(GND) U124.2(GND) U131.2(GND) U132.6(GND) U132.17(EP) U173.25(GND) U173.33(EP) U213.3(GND) U247.3(GND) U249.2(GND) U251.2(GND) U252.2(GND) U255.2(GND) U258.2(GND) ; also on sheet 11 12 13 14 15 16 17 18 20 21 22 23 24 25 26 27 28 29 30 31 32 33 34 35 40 41 42 43 44 45 46 47 48 49 50 51 52 53 54 55 56 57 58 59 60 61 62 63 64 65 66 67 68 69 70 71 72 73 76 77 78 79 81 82 83 84
VIN_MON_PORZ: R591.2 R600.1 U255.1(A)
VINPUT: R620.1 ; also on sheet 64 65 66 67
AUDIO_MUX_SEL: U43.14(P14) ; also on sheet 48
CAN_STB: R794.1 ; also on sheet 30 81
CANUART_MUX1_SEL1: U173.16(P17) ; also on sheet 20
CANUART_MUX2_SEL1: U173.15(P16) ; also on sheet 20
CANUART_MUX_SEL0: U173.14(P15) ; also on sheet 20 35
CDCI1_OE1/OE4: U43.12(P12) ; also on sheet 32
CDCI1_OE2/OE3: U43.13(P13) ; also on sheet 32
CDCI2_RSTz: U173.12(P13) ; also on sheet 33
CODEC_RSTz: U132.2(P0) ; also on sheet 82
CODEC_SPARE1: TP230.1(TP) U132.3(P1)
CSI2_EXP_A_GPIO0: U76.3(P1) ; also on sheet 31
CSI2_EXP_A_GPIO1: U76.4(P2) ; also on sheet 31
CSI2_EXP_A_GPIO3: U76.5(P3) ; also on sheet 31
CSI2_EXP_B_GPIO1: U76.7(P4) ; also on sheet 31
CSI2_EXP_B_GPIO2: U76.8(P5) ; also on sheet 31
CSI2_EXP_B_GPIO3: U76.9(P6) ; also on sheet 31
CSI2_EXP_B_GPIO4: U76.10(P7) ; also on sheet 31
CSI2_EXP_RSTz: U76.2(P0) ; also on sheet 31
CTRL_PM_I2C_OE#: U173.9(P10) ; also on sheet 63
DP0_PWR_SW_EN: U18.2(P0) ; also on sheet 68
DP1_PWR_SW_EN: U18.3(P1) ; also on sheet 68
EMMC_RSTz: TP289.1(TP) U213.4(Y) ; also on sheet 41
EXP_MUX2: U43.15(P15) ; also on sheet 30
EXP_MUX3: U43.16(P16) ; also on sheet 30
EXP_RSTz: TP48.1(TP) U39.4(Y) ; also on sheet 30
GESI_EXP_PHY_RSTz: R200.2 R204.1 U39.2(B) U43.17(P17)
GESI_GPIO_RGMII1_RST#: R778.1 ; also on sheet 30
GPIO_eDP_ENABLE: U18.4(P2) ; also on sheet 61
GPIO_LIN_EN: U173.7(P06) ; also on sheet 30 46
GPIO_RGMII1_RST#: R777.1 ; also on sheet 56
GPIO_uSD_PWR_EN: U173.3(P02) ; also on sheet 40
H_MCU_PORz: U258.1(A) ; also on sheet 69
H_SOC_PORz: U252.1(A) ; also on sheet 69
I2C0_IOEXP_INT#: R229.2 U43.22(~{INT}) U173.32(~{INT}) ; also on sheet 21
I2C0_SCL: U43.19(SCL) U173.29(SCL) ; also on sheet 20 32 33 34 58 59
I2C0_SDA: U43.20(SDA) U173.30(SDA) ; also on sheet 20 32 33 34 58 59
I2C3_SCL: U132.12(SCL) ; also on sheet 20 82
I2C3_SDA: U132.13(SDA) ; also on sheet 20 82
I2C4_SCL: U18.12(SCL) ; also on sheet 20 61
I2C4_SDA: U18.13(SDA) ; also on sheet 20 61
I2C5_SCL: U76.12(SCL) ; also on sheet 20 31
I2C5_SDA: U76.13(SDA) ; also on sheet 20 31
IOEXP1_A0: R250.2 R251.1 U43.18(ADDR)
IOEXP2_A0: R771.1 R773.1 U173.26(ADDR)
IOEXP3_ADDR: R628.2 R638.1 U132.16(ADDR)
IOEXP3_INT#: R616.1 U132.11(~{INT})
IOEXP4_ADDR: R97.2 R98.1 U18.16(ADDR)
IOEXP4_INT#: R72.1 U18.11(~{INT})
IOEXP5_ADDR: R453.1 R459.2 U76.16(ADDR)
IOEXP5_INT#: R443.1 U76.11(~{INT}) ; also on sheet 20
JTAG_RESETz: R588.1 R1157.1 ; also on sheet 48
LM5140/LM5143/LM5141_PG: R1190.2 R1191.2 R1192.2 R1193.2 U255.3(B)
LM5140_PG1: R1153.1 R1193.1 ; also on sheet 65
LM5140_PG1/LM5140_PG2: R1153.2 R1155.2 U247.1(A)
LM5140_PG2: R1155.1 ; also on sheet 65
LM5141_PG: R1191.1 ; also on sheet 66
LM5143_PG1: R1192.1 ; also on sheet 67
LM5143_PG2: R1190.1 ; also on sheet 67
MCAN3_STB#: R792.1 ; also on sheet 50
MCAN5_STB: R788.1 ; also on sheet 50
MCU_OSPI1_CLK: R457.2 U79.B2(C) ; also on sheet 16
MCU_OSPI1_CS0: R1133.1 U79.C2(S#) ; also on sheet 16
MCU_OSPI1_D0: R1125.1 U79.D3(DQ0) ; also on sheet 16
MCU_OSPI1_D1: R1124.1 U79.D2(DQ1) ; also on sheet 16
MCU_OSPI1_D2: R1130.1 U79.C4(W#/DQ2) ; also on sheet 16
MCU_OSPI1_D3: R1126.1 U79.D4(DQ3/HOLD#) ; also on sheet 16
MCU_OSPI1_DQS: R477.2 ; also on sheet 16
MCU_OSPI1_LBCLKO: R477.1 ; also on sheet 16
MCU_PERIPH_1V8_RSTz: TP193.1(TP) U79.A4(RESET#/DNU) U103.4(Y)
MCU_PERIPH_RSTz: R559.2 R565.2 U103.2(A) ; also on sheet 17 18 44 62
MCU_PORZ: TP221.1(TP) U124.4(Y) ; also on sheet 18
MCU_PORZ_OUT: R559.1 ; also on sheet 18 55 69
MCU_RESETSTATZ: R565.1 ; also on sheet 18
MCU_RESETZ: TP189.1(TP) U101.4(Y) ; also on sheet 18
PB_MCU_PORz: U258.6(C) ; also on sheet 35
PB_MCU_RESETz: U101.2(B) ; also on sheet 35
PB_PORz: U247.2(B) ; also on sheet 35
PB_RESETz: U249.1(A) ; also on sheet 35
PCIe0_4L_EP_RST_EN: U43.8(P07) ; also on sheet 59
PCIe0_4L_MODE_SEL: U43.5(P04) ; also on sheet 35 59
PCIe0_4L_PERSTz: U43.6(P05) ; also on sheet 59
PCIe0_4L_PRSNT#: U43.11(P11) ; also on sheet 59
PCIe0_4L_RC_RSTz: U43.7(P06) ; also on sheet 59
PCIe0_PORz: U251.3(B) ; also on sheet 59
PCIe1_2L_EP_RST_EN: U43.4(P03) ; also on sheet 60
PCIe1_2L_MODE_SEL: U43.1(P00) ; also on sheet 35 60
PCIe1_2L_RC_RSTz: U43.3(P02) ; also on sheet 60
PCIe1_4L_PERSTz: U43.2(P01) ; also on sheet 60
PCIe1_4L_PRSNT#: U43.10(P10) ; also on sheet 60
PCIe1_PORz: U251.6(C) ; also on sheet 60
PERIPH_RSTz: R964.2 U18.1(~{RESET}) U43.24(~{RESET}) U76.1(~{RESET}) U132.1(~{RESET}) U173.28(~{RESET}) U213.2(A) ; also on sheet 30
PORZ: TP182.1(TP) U252.4(Y) ; also on sheet 18
R_CAN_STB: R788.2 R792.2 R794.2 U173.8(P07)
R_GPIO_RGMII1_RST#: R777.2 R778.2 U173.1(P00)
RESET_REQZ: TP321.1(TP) U249.4(Y) ; also on sheet 18
RESETSTATZ: R964.1 ; also on sheet 18 30 62
SOC_PORZ_OUT: U39.1(A) ; also on sheet 18 30 32 43 51 56 59 60 62 69
SYS_PWR_PG: U255.4(Y) U258.3(B) ; also on sheet 35 73
TA_PORZn: U124.3(B) U251.1(A) ; also on sheet 47 63
TA_RESETz: U249.3(B) ; also on sheet 47 63
USB2.0_MUX_SEL: U173.13(P14) ; also on sheet 24
USBC_MODE_SEL0: U173.6(P05) ; also on sheet 35 53
USBC_MODE_SEL1: U173.5(P04) ; also on sheet 35 53
USBC_PWR_EN: U173.4(P03) ; also on sheet 53
USER_INPUT1: U173.22(P25) ; also on sheet 35
USER_LED1: U173.23(P26) ; also on sheet 35
USER_LED2: U173.24(P27) ; also on sheet 35
VDA_MCU_1V8: C1138.2 C1175.2 C1183.1 C1184.1 U124.5(VCC) U252.5(VCC) U258.5(VCC) ; also on sheet 21 25 69 74
VSYS3V3_MON_CT: C435.1 U131.4(CT)
VSYS3V3_MON_MR#: R631.2 U131.3(~{MR})
VSYS3V3_MON_RESET#: R618.1 U131.1(~{RESE}T)
VSYS_3V3: C400.1 C426.2 C1123.1 C1137.1 C1185.2 R591.1 R614.2 R631.1 U122.5(VDD) U131.5(SENSE) U131.6(VDD) U247.5(VCC) U251.5(VCC) U255.5(VCC) ; also on sheet 22 23 35 40 47 49 62 63 65 66 67 68 69 73 75 76 77 78 79
VSYS_IO_1V8: C770.1 R229.1 U213.5(VCC) ; also on sheet 30 32 33 34 41 42 61 65 75
VSYS_IO_3V3: C64.2 C184.1 C188.2 C300.2 C433.2 C575.2 C717.2 R72.2 R98.2 R200.1 R250.1 R443.2 R453.2 R616.2 R638.2 R771.2 R1161.2 U18.14(VCCP) U18.15(VCCI) U39.5(VCC) U43.21(VCCP) U43.23(VCCI) U76.14(VCCP) U76.15(VCCI) U132.14(VCCP) U132.15(VCCI) U173.27(VCCP) U173.31(VCC) ; also on sheet 18 20 22 24 29 30 31 32 33 35 40 41 42 43 45 46 48 50 51 53 56 57 58 59 60 61 65 66 68 75 81 82
VSYS_MCUIO_1V8: C376.1 C1095.1 C1096.1 C1098.1 R1124.2 R1125.2 R1126.2 R1130.2 R1133.2 U79.B4(VCC) U103.5(VCC) ; also on sheet 17 21 53 62 65 75
VSYS_MCUIO_3V3: C373.2 C1124.1 R563.1 R593.2 U101.5(VCC) U249.5(VCC) ; also on sheet 16 17 18 21 22 23 35 43 44 48 49 55 62 65 68 75
N26384207: U251.4(Y) U252.6(C)
N26384397: R563.2 U101.1(A)
N26384556: C405.1 R615.1 R620.2 U122.3(SENSE)
N27366714: U247.4(Y) U252.3(B)
N30006402: R614.1 R618.2 U255.6(C)
N30969363: U124.1(A) U258.4(Y)
N34186667: R600.2 U122.1(OUT)
N35327993: R1157.2 R1161.1 U249.6(C)
N35328046: R588.2 R593.1 U124.6(C)

Not connected (* = marked no-connect by the designer): U18 5(P3)* 7(P4)* 8(P5)* 9(P6)* 10(P7)*; U79 A2(DNU1)* A3(DNU2)* A5(DNU3)* B1(DNU4)* B5(DNU5)* C1(DNU6)* C3(DNU7)* C5(DNU8)* D1(DNU9)* D5(DNU10)* E1(DNU11)* E2(DNU12)* E3(DNU13)* E4(DNU14)* E5(DNU15)*; U103 1(NC)*; U132 4(P2)* 5(P3)* 7(P4)* 8(P5)* 9(P6)* 10(P7)*; U173 2(P01)* 10(P11)* 11(P12)* 17(P20)* 18(P21)* 19(P22)* 20(P23)* 21(P24)*; U213 1(NC)*

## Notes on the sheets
sheet 36
- RESET INPUTS
- Under Voltage Monitor (VINPUT)
- MCU PORZ
- MCU_RESET
- To SOC
- 40us delay by default
- VINPUT < 21.50V asserts PORz
- To Bypass U172 circuit Isolate R918
- SOC PORZ
- SOC RESET
- From PCIe connectors
sheet 37
- RESET OUTPUTS
sheet 38
- GPIO  EXPANDERS
- I2C GPIO  EXPANDER1
- I2C GPIO  EXPANDER3
- [Unused]
- I2C ADDRESS: 0x20
- 7'b I2C Address- 0x20
- I2C GPIO  EXPANDER4
- I2C GPIO  EXPANDER2
- I2C ADDRESS: 0x20
- I2C ADDRESS: 0x22
- I2C GPIO  EXPANDER5
- I2C ADDRESS: 0x20
sheet 39
- SPI NOR Flash
- O/P from SoC
- To match timing
- I/P to SoC
